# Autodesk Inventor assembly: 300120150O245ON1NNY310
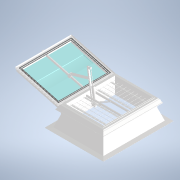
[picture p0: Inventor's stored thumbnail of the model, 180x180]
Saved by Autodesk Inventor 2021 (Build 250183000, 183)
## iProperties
Category: PARTsolutions
Company: KINGSPAN
Created: 2026-04
Part Number: 300120150O245ON1NNY310
Catalog Web Link: www.3dfindit.com
Description: LK neo plus-
Vendor: KINGSPAN
Document SubType Name: Assembly
Designer: psAdmin
Manufacturer: KINGSPAN
Mass: 365950 g
Surface Area: 173517 cm^2
Volume: 365950 cm^3
Density: 1 g/cm^3
Title: LKneoplus120150O245N1NNY31
Author: Cadenas PARTsolutions
PSOL_IDENT_0: {$CADENAS_DATA/23d-libs/kingspan_kla/light_dome_classic_neoplus/light_dome_classic_neoplus_asmtab.pr
PSOL_IDENT_1: j},271 {VTYP=3D},{STYP=ASSTAB},{NB=300120150O245ON1NNY310},{LINA=LKneoplus120150O245N1NNY31},{NN=LK
PSOL_IDENT_2: neo plus},{DATE=05.11.2025 13:48:11},{GEOMDATE=13.01.2025 13:06:59},{VERSION=},{LINEID=10},{WBVAR=LO
PSOL_IDENT_3: DLEVEL,L,W,TG,TS,DP,OP,OC,GCW,SD,IPM,EVADSS,SSSO,BA,INS,RT},{WBNUMERIC=W,RT}  {NB=300120150O245ON1NN
PSOL_IDENT_4: Y310},{LINA=LKneoplus120150O245N1NNY31},{KT=DUMMY},{IDNR=},{PN=LK neo plus},{LODLEVEL=300},{L=120},{
PSOL_IDENT_5: W=150},{DRIVE=1},{WX=120,150,180,240,270,300},{TG=O},{TS=2},{WF=included},{DP=4},{OP=5},{OC=O},{SM=Y
PSOL_IDENT_6: },{GCW=N},{SD=1},{IPM=N},{EVADSS=N},{SSSO=Y},{BA=3},{INS=1},{INSX='1','i - insulation','2','ih - enh
PSOL_IDENT_7: anced insulation'},{BAX='3', 'AK50 PVC', '2', 'AK30 PVC' , '7' , 'AK30 AL/ST', '8', 'AK40 AL/ST', '9'
PSOL_IDENT_8: , 'AK50 AL/ST', '13' , 'AK30 AL/AL', '14' , 'AK40 AL/AL', '15' , 'AK50 AL/AL', '16' , 'AK50 ST-TG',
PSOL_IDENT_9: '10', 'AK30 ST', '11' , 'AK40 ST', '12', 'AK50 ST'},{UVD=1.9},{UVDU=calculated by excell tool},{LT=
PSOL_IDENT_10: 47},{GV=62},{SI=22},{WFX='Y','Yes','N','No'},{OPX='5','Pneumatic - NRWG F.6 LK'},{TSX='1','PC-st 20/
PSOL_IDENT_11: 7 + 1 shell','2','3‐shelled','3','3‐shelled with heat‐stop coating'},{LX=1200},{XWX=1500},{ANG=9.500
PSOL_IDENT_12: 6},{ROT=-15},{PPATH=parts/light_dome_classic_asmtpl.prj},{IBM=LKneoplus120150O245N1NNY31},{SFX='Y','
PSOL_IDENT_13: Yes','N','No'},{DPX='3', 'Fixed','1', 'Natural ventilation'  ,'4','NSHE', '2', 'NSHEV'},{OCX='O', 'O
PSOL_IDENT_14: pen', 'C', 'Closed'},{SMX='Y','Yes'},{VERPRA=3},{EVADSSX='Y', 'Yes', 'N', 'No'},{RT=0},{SDX='1', 'RS
PSOL_IDENT_15: M - round bar fall-through protection mat', '2'  , 'EAD - laser cut fall-through protection mat', '3'
PSOL_IDENT_16: , 'HDS - fall through/hale protection and shading system'}
NB: 300120150O245ON1NNY310
NN: LK neo plus
NBSYN: $LODLEVEL.$L.$W.$TG.$TS.$DP.$OP.$OC.$GCW.$SD.$IPM.$EVADSS.$SSSO.$BA.$INS.$RT.
LINA: LKneoplus120150O245N1NNY31
CATALOG: Light + Air
PN: LK neo plus
LODLEVEL: 300
L: 120
W: 150
TG: opal
TS: 3‐shelled
WF: included
DP: NSHE
OP: Pneumatic - NRWG F6 LK
OC: Open
GCW: No
SD: RSM - round bar fall-through protection mat
IPM: No
EVADSS: No
BA: AK PVC 50
INS: i - insulation
UVD: 1.9
LT: 47
GV: 62
SI: 22
RT: 0
SUPPLIER: KINGSPAN
ARTICLENO: 300120150O245ON1NNY310
BOMINFO: LKneoplus120150O245N1NNY31
CREATOR: CADENAS GmbH
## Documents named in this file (12)
- e:\temp\worker_COMMON_207\temp\tmp_920_88_Ehmb0\format_1\300120150O245ON1NNY310.iam
- e:\temp\worker_COMMON_207\temp\tmp_920_88_Ehmb0\format_1\Light dome classic(30012015045320)_part_1_neoplus.ipt
- e:\temp\worker_COMMON_207\temp\tmp_920_88_Ehmb0\format_1\Light dome classic(3001201503Y45O)_part_2_neoplus.ipt
- e:\temp\worker_COMMON_207\temp\tmp_920_88_Ehmb0\format_1\Light dome classic(300120150)_part_8_neoplus.ipt
- e:\temp\worker_COMMON_207\temp\tmp_920_88_Ehmb0\format_1\Light dome classic(30012015045)_part_9_neoplus.ipt
- e:\temp\worker_COMMON_207\temp\tmp_920_88_Ehmb0\format_1\Light dome classic(30012015045)_part_9_sec_neoplus.ipt
- e:\temp\worker_COMMON_207\temp\tmp_920_88_Ehmb0\format_1\Light dome classic(30012015045O)_part_3_neoplus.ipt
- e:\temp\worker_COMMON_207\temp\tmp_920_88_Ehmb0\format_1\Light dome classic(300120150O3)_part_4_neoplus.ipt
- e:\temp\worker_COMMON_207\temp\tmp_920_88_Ehmb0\format_1\Light dome classic(300120150)_part_5_neoplus.ipt
- e:\temp\worker_COMMON_207\temp\tmp_920_88_Ehmb0\format_1\Light dome classic(300120150)_part_6_neoplus.ipt
- e:\temp\worker_COMMON_207\temp\tmp_920_88_Ehmb0\format_1\Light dome classic(30012015045)_part_11_neoplus.ipt
- e:\temp\worker_COMMON_207\temp\tmp_920_88_Ehmb0\format_1\Light dome classic(300120150453O)_part_10_neoplus.ipt
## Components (14 placed, 11 different names)
1. Light dome classic(30012015045320)_part_1_neoplus:1
2. Light dome classic(3001201503Y45O)_part_2_neoplus:1
3. Light dome classic(300120150)_part_8_neoplus:1
4. Light dome classic(300120150)_part_8_neoplus:2
5. Light dome classic(300120150)_part_8_neoplus:3
6. Light dome classic(300120150)_part_8_neoplus:4
7. Light dome classic(30012015045)_part_9_neoplus:1
8. Light dome classic(30012015045)_part_9_sec_neoplus:1
9. Light dome classic(30012015045O)_part_3_neoplus:1
10. Light dome classic(300120150O3)_part_4_neoplus:1
11. Light dome classic(300120150)_part_5_neoplus:1
12. Light dome classic(300120150)_part_6_neoplus:1
13. Light dome classic(30012015045)_part_11_neoplus:1
14. Light dome classic(300120150453O)_part_10_neoplus:1
